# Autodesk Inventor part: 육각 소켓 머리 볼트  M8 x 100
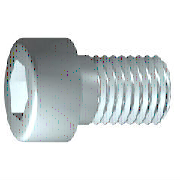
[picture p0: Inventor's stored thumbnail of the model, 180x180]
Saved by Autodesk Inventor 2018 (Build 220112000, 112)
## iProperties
IsCustomPart: 1
Created: 2012-02
Part Number: 육각 소켓 머리 볼트  M8 x 100
Material: 강철, 연강
Description: 6각 소켓 머리 캡 나사
Document SubType Name: Modeling
Standard: ISO 4762
Designer: mdu-01
Standard Revision: Fourth edition 2004-03-01
Standards Organization: ISO
Language: ko-KR
Size Designation: M8 x 12
Categories: <MemberInstance><Categories><Category DisplayName="조임쇠" InternalName="e4da775c-781d-43d5-af7c-5136215cf5a6" Mnemonic="FSTN"><Category DisplayName="볼트" InternalN
Density: 7.75 g/cm^3
Appearance: 강철
Author: mdu-01
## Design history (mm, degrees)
sketch "스케치1"
  geometry: L1 (-2, 0)-(100, 0); L2 (100, 0)-(100, 4); L3 (100, 4)-(91.125, 4); L4 (91.125, 4)-(90.358, 4); L5 (90.358, 4)-(0, 4); L6 (0, 4)-(0, 6.5); L7 (0, 6.5)-(-8, 6.5); L8 (-8, 6.5)-(-8, 3.464); L9 (-8, 3.464)-(-4, 3.464); L10 (-4, 3.464)-(-2, 0); L11 (-29.6, 0)-(121.6, 0) reference; L12 (0, -1.3)-(0, 7.8) reference; L13 (91.125, 4)-(0, 4)
  constraints: 22 end point, 6 parallel, 2 collinear, 2 perpendicular, 1 horizontal, 1 point on line
  dimensions: "d1" = 8.875 distance from line of L3.end L2 (= GEL); "d2" = 0.76691 distance of L4.end L3.end (computed from GAL); "d3" = 8 distance between parallel lines of L8 L6 (= KOH); "d4" = 4 distance of L8.end L9.end (= INTI); "d5" = 60 deg angle of L10 L1; "d6" = 8 diameter of L3 L1 (= GD); "d7" = 8 diameter of L5 L1 (= BDM); "d8" = 6.9282 diameter of L9 L1 (= 1.1547 x SW); "d9" = 13 diameter of L7 L1 (= KOD); "d26" = 100 distance between parallel lines of L12 L2
revolve "본체" sketch "스케치1" stored, may be unused: angle "d10" = 90 deg
sketch "스케치2"
  geometry: L1 (0, -9.1)-(0, 9.1) reference; L2 (-9.1, 0)-(9.1, 0) reference; L3 (3.464, 0)-(1.732, -3); L4 (1.732, -3)-(-1.732, -3); L5 (-1.732, -3)-(-3.464, 0); L6 (-3.464, 0)-(-1.732, 3); L7 (-1.732, 3)-(1.732, 3); L8 (1.732, 3)-(3.464, 0); 2 further points
  constraints: 12 end point, 1 coincident, 1 horizontal alignment, 1 point on line, 12 other
extrude "슬롯" join sketch "스케치2" stored distance "d11" = 10; taper "d12" = 0 deg
workplane "Work Plane1"
fillet "Fillet2" dims "d30" = 0.1 (= R)
body "Solid1"
fillet "모깎기1" dims "d17" = 0.8 (= RR)
feature "스레드" dims "d13" = 20, "d14" = 0
chamfer "모따기1" distance "d15" = 0.76681 (= -0.5 x SPD + 0.5 x GD); stored, may be unused: second distance "d16" = 0.76681 (= GUL), angle "d27" = 45 deg
other parameters: "GD" = 8 [user parameter; used in 2 equation terms], "NLG" = 12 [user parameter], "GEL" = 8.875 [user parameter; used in 1 equation term], "KOD" = 13 [user parameter; used in 1 equation term], "KOH" = 8 [user parameter; used in 1 equation term], "INTI" = 4 [user parameter; used in 1 equation term], "GAL" = 0.76681 (= 0.61345 x PTC) [user parameter; used in 1 equation term], "GUL" = 0.76681 (= 0.61345 x PTC) [user parameter; used in 1 equation term], "BDM" = 8 (= NND) [user parameter; used in 1 equation term], "SW" = 6 [user parameter; used in 2 equation terms], "RR" = 0.8 [user parameter; used in 1 equation term], "SPD" = 6.46637 (= NND - 1.2269 x PTC) [user parameter; used in 1 equation term], "d19" = 0, "d28" = 0, "d29" = 0, "R" = 0.1 [user parameter; used in 1 equation term], "TOA" = 30 deg [user parameter], "GD1" = 6.46637 (= THREADDIA - 1.2269 x PTC) [user parameter], "THREADDIA" = 8 [user parameter; used in 1 equation term], "FAWI" = 45 deg [user parameter], "TPU" = 8 (computed from PTC) [user parameter], "PTC" = 1.25 [user parameter; used in 5 equation terms], "NND" = 8 [user parameter; used in 2 equation terms], "E0" = 6.93 (= 1.155 x SW) [user parameter]
